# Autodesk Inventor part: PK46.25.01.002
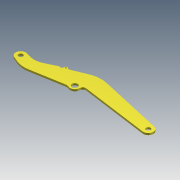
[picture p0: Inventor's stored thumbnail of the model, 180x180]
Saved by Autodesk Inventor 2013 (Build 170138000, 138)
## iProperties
Created: 2005-04
Part Number: PK46.25.01.002
Material: Steel, Mild
Document SubType Name: Modeling
Designer: salex
Manufacturer: Standard
Standards Organization: Custom
Density: 7.86 g/cm^3
Author: salex
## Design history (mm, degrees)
derived "PK46.25.01.001.ipt"
sketch "Эскиз2"
  geometry: L1 (-683.397, 20.778)-(-278.697, 257.272) reference; L2 (-656.553, 82.599)-(-660.644, 34.074); L3 (-613.061, 106.82)-(-571.94, 85.91); L4 (-1314.556, -273.082)-(1438.923, 110); L5 (-1314.556, -273.082)-(-1346.937, -40.338); L6 (-626.659, 80.078)-(-591.52, -172.489); C1 r 15 at (-626.659, 80.078); A1 r 110 centre (-1314.556, -273.082) between (-1296.278, -164.612) and (-1342.621, -379.442) reference; A2 r 110 centre (1438.923, 110) between (1438.923, 0) and (1448.298, 219.6) reference; A3 r 30 centre (-626.659, 80.078) between (-613.061, 106.82) and (-656.553, 82.599)
  constraints: 10 end point, 3 point on line, 2 centre point, 2 perpendicular, 2 point on circle, 2 tangent, 1 coincident
  dimensions: "d33" = 30 diameter of C1; "d34" = 30 radius of A3; "d35" = 255 distance from line of C1.centre L4; "d37" = 730 distance from line of C1.centre L5; "d38" = 55 distance from line of L3.end L6; "d39" = 40 distance from line of L2.end L6
extrude "Выдавливание2" join sketch "Эскиз2" stored distance "d40" = 10; taper "d41" = 0 deg
fillet "Сопряжение1" dims "d42" = 20
body "Solid1"
tag "TaggingFeature2"
feature "DerivedBody::PK46.25.01.001.ipt" dims "d32" = 10
